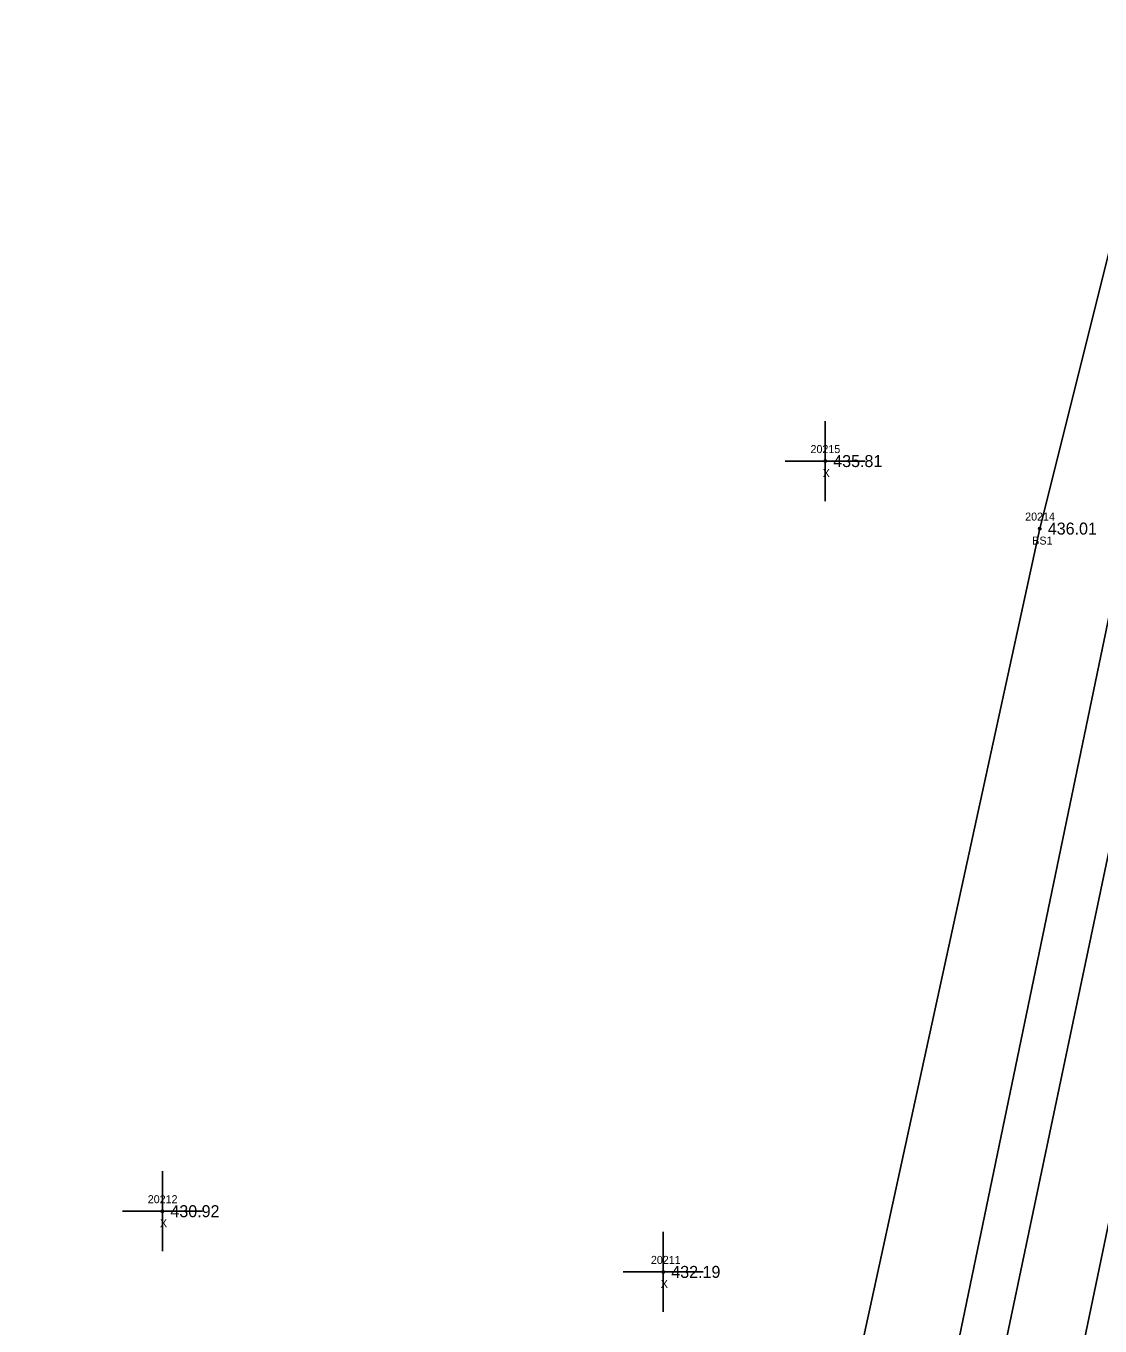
# Model space of a CAD drawing. Extents: x 1755707 to 1756750, y 975854 to 977363.
# Drawn here: x 1756101.8 to 1756236.1, y 976750.2 to 976912.7 of the extents above; entities that cross this region are included whole.
import ezdxf

# ---------------------------------------------------------------- set-up
doc = ezdxf.new("R2010")
doc.units = 0
for name, color, linetype in [('RD_DTM_BkLn1', 7, 'Continuous'), ('RD_DTM_BkLn2', 7, 'Continuous'), ('RD_DTM_BkLn_txCode', 7, 'Continuous'), ('RD_EX_Misc', 7, 'Continuous'), ('RD_EX_Misc_txCode', 7, 'Continuous'), ('RD_EX_Road', 7, 'Continuous'), ('RD_EX_TX_Misc_ELEV', 7, 'Continuous'), ('RD_SMD_Locator', 7, 'Continuous')]:
    doc.layers.add(name, color=color, linetype=linetype)

msp = doc.modelspace()

# ---------------------------------------------------------------- linework, layer by layer
at = {"layer": 'RD_DTM_BkLn1'}
msp.add_lwpolyline([(1756212.24, 976646.92), (1756233.31, 976744.58), (1756253.87, 976843.36), (1756274.18, 976942.87), (1756294.7, 977044.28), (1756314.7, 977141.54), (1756335.65, 977241.96), (1756357.9, 977342.03)], dxfattribs=at)
at = {"layer": 'RD_DTM_BkLn2'}
for points in [[(1756101.82, 976704.9), (1756150.92, 976716.16), (1756211.72, 976728.04), (1756216.23, 976737.89), (1756238.86, 976847.03), (1756261.79, 976945.44), (1756283.19, 977044.99), (1756303.06, 977145.95), (1756325.46, 977245.55), (1756346.55, 977344.09)], [(1756101.82, 976704.9), (1756144.73, 976723.58), (1756149.68, 976727.6), (1756152.89, 976726.7), (1756204.3, 976738.63), (1756228.54, 976849.91), (1756252.92, 976947.37), (1756266.62, 977008.29)]]:
    msp.add_lwpolyline(points, dxfattribs=at)
at = {"layer": 'RD_EX_Misc'}
for p, q in [((1756201.72, 976853.35), (1756201.72, 976863.35)), ((1756196.72, 976858.35), (1756206.72, 976858.35)), ((1756118.87, 976759.59), (1756118.87, 976769.59)), ((1756113.87, 976764.59), (1756123.87, 976764.59)), ((1756181.48, 976752), (1756181.48, 976762)), ((1756176.48, 976757), (1756186.48, 976757))]:
    msp.add_line(p, q, dxfattribs=at)
at = {"layer": 'RD_EX_Road'}
msp.add_lwpolyline([(1756212.24, 976646.92), (1756202.87, 976648.96), (1756215.01, 976705.04), (1756220.09, 976730.75), (1756223.91, 976746.46), (1756244.6, 976844.81), (1756265.35, 976944.71), (1756286.1, 977045.83), (1756306.04, 977143.32), (1756326.71, 977243.79), (1756348.97, 977343.58)], dxfattribs=at)
at = {"layer": 'RD_SMD_Locator'}
for centre in [(1756201.72, 976858.35), (1756228.54, 976849.91), (1756118.87, 976764.59), (1756181.48, 976757)]:
    msp.add_circle(centre, 0.15, dxfattribs=at)

# ---------------------------------------------------------------- texts
at = {"layer": 'RD_DTM_BkLn_txCode'}
for s, p in [('20214', (1756226.71, 976850.91)), ('BS1', (1756227.6, 976847.91))]:
    msp.add_text(s, height=1, dxfattribs=at).set_placement(p)
at = {"layer": 'RD_EX_Misc_txCode'}
for s, p in [('20215', (1756199.88, 976859.35)), ('X', (1756201.4, 976856.35)), ('20212', (1756117.04, 976765.59)), ('X', (1756118.56, 976762.59)), ('20211', (1756179.93, 976758)), ('X', (1756181.16, 976755))]:
    msp.add_text(s, height=1, dxfattribs=at).set_placement(p)
at = {"layer": 'RD_EX_TX_Misc_ELEV'}
for s, p in [('435.81', (1756202.72, 976857.6)), ('436.01', (1756229.54, 976849.16)), ('430.92', (1756119.87, 976763.84)), ('432.19', (1756182.48, 976756.25))]:
    msp.add_text(s, height=1.5, dxfattribs=at).set_placement(p)

doc.saveas('drawing.dxf')
